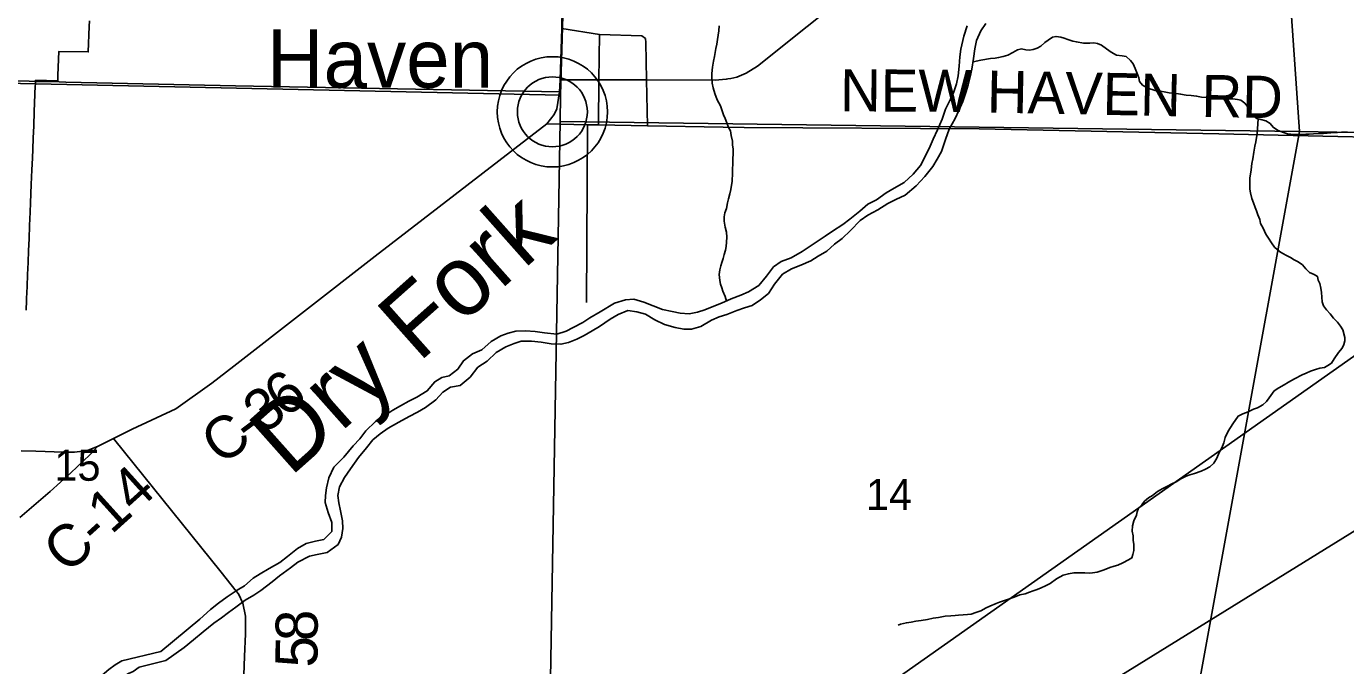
# Model space of a CAD drawing. Extents: x -7.5 to 26.5, y 3.5 to 25.5.
# Drawn here: x -1.65 to 0.131, y 22.311 to 23.173 of the extents above; entities that cross this region are included whole.
import ezdxf

# ---------------------------------------------------------------- set-up
doc = ezdxf.new("R2010")
doc.units = 0
for name, color, linetype in [('GM_X_Corporation', 7, 'Continuous'), ('GM_X_County_Road', 7, 'Continuous'), ('GM_X_County_Road_Text', 7, 'Continuous'), ('GM_X_Minor_River', 7, 'Continuous'), ('GM_X_Minor_River_Text', 7, 'Continuous'), ('GM_X_Section_Text', 7, 'Continuous'), ('GM_X_Township_Road', 7, 'Continuous'), ('GM_X_Unincorporated', 7, 'Continuous'), ('GM_X_Unincorporated_Location', 7, 'Continuous'), ('GM_X_Unincorporated_Text', 7, 'Continuous'), ('SH_Text', 7, 'Continuous')]:
    doc.layers.add(name, color=color, linetype=linetype)

msp = doc.modelspace()

# ---------------------------------------------------------------- linework, layer by layer
at = {"layer": 'GM_X_Corporation'}
for points in [[(-2.147, 24.1207), (-0.8988, 24.09), (-0.9286, 23.0807), (-2.1999, 23.1078)], [(-0.8988, 24.09), (-0.0024, 24.0614), (0.0689, 23.0315), (-0.9291, 23.0451), (-0.9286, 23.0807)], [(-0.0024, 24.0614), (1.0957, 24.0219), (1.0735, 23.0136), (0.0689, 23.0315)], [(-2.1999, 23.1078), (-0.9286, 23.0807), (-0.9291, 23.0451), (-0.9461, 22.0601), (-2.2479, 22.1217)], [(0.0689, 23.0315), (-0.1108, 22.0429), (-0.9461, 22.0601), (-0.9291, 23.0451)], [(1.0735, 23.0136), (1.0508, 22.0159), (-0.1108, 22.0429), (0.0689, 23.0315)]]:
    msp.add_lwpolyline(points, close=True, dxfattribs=at)
msp.add_lwpolyline([(-1.5642, 23.1808), (-1.5646, 23.1731), (-1.566, 23.1389), (-1.6056, 23.1397), (-1.6069, 23.1077), (-1.6073, 23.1001), (-1.6372, 23.1007), (-1.6374, 23.095), (-1.6375, 23.0932), (-1.6389, 23.0585), (-1.6397, 23.0394), (-1.6404, 23.0224), (-1.641, 23.0078), (-1.6415, 22.9955), (-1.6422, 22.9797), (-1.643, 22.9601), (-1.644, 22.9353), (-1.6445, 22.9228), (-1.6452, 22.9048), (-1.646, 22.8869), (-1.6466, 22.8709), (-1.6473, 22.8548), (-1.6479, 22.8387), (-1.6486, 22.8226), (-1.6493, 22.8065), (-1.6494, 22.8036), (-1.6499, 22.7904)], dxfattribs=at)
at = {"layer": 'GM_X_County_Road'}
for points in [[(-0.9268, 23.1706), (-0.9225, 23.418), (-0.9241, 23.4397), (-0.9294, 23.4683), (-0.9349, 23.4993), (-0.9361, 23.5122), (-0.9345, 23.5422), (-0.9252, 23.629), (-0.9207, 23.6517), (-0.9185, 23.6763), (-0.9147, 23.7286), (-0.9035, 24.1114), (-0.8973, 24.4)], [(-0.7027, 23.1025), (-0.6986, 23.1032), (-0.6906, 23.1047), (-0.6779, 23.1104), (-0.6624, 23.1199), (-0.5287, 23.2271), (-0.5239, 23.2334), (-0.5217, 23.2447), (-0.5167, 23.5532), (-0.5166, 23.5545), (-0.5162, 23.5554), (-0.5157, 23.556), (-0.5147, 23.5562), (-0.4415, 23.5545), (-0.4014, 23.5536)], [(-0.9469, 23.0417), (-0.937, 23.0547), (-0.9337, 23.0622), (-0.9298, 23.0853), (-0.9292, 23.1013), (-0.9268, 23.1706)], [(-1.9187, 23.1051), (-1.6459, 23.0994), (-1.6361, 23.0992)], [(-1.6361, 23.0992), (-1.6055, 23.0985), (-1.5964, 23.0983)], [(-1.5964, 23.0983), (-1.3671, 23.0933), (-0.9298, 23.0853)], [(-0.9292, 23.1013), (-0.8766, 23.1012), (-0.8125, 23.1011), (-0.7199, 23.101), (-0.7047, 23.1021), (-0.7027, 23.1025)], [(-1.6568, 22.6007), (-1.6367, 22.6004), (-1.5995, 22.5991), (-1.5848, 22.5989), (-1.5737, 22.6001), (-1.5662, 22.6016), (-1.5536, 22.6067), (-1.5321, 22.6175), (-1.5067, 22.63), (-1.4479, 22.6575), (-1.3991, 22.6922), (-1.3695, 22.7151), (-1.1787, 22.8635), (-0.9469, 23.0417)], [(-0.9469, 23.0417), (-0.8922, 23.0406), (-0.8774, 23.0404), (-0.8113, 23.0391), (-0.7088, 23.0372), (-0.6806, 23.037)], [(-0.6806, 23.037), (-0.3636, 23.035), (-0.0398, 23.0286), (0.3216, 23.0203), (0.4815, 23.0211), (0.5343, 23.0188), (0.5601, 23.0196)], [(-1.5321, 22.6175), (-1.3864, 22.4372), (-1.3664, 22.4116)], [(-1.6586, 22.5107), (-1.6175, 22.5459), (-1.5895, 22.5709), (-1.5639, 22.5954), (-1.5536, 22.6067)], [(-1.3664, 22.4116), (-1.3634, 22.4078), (-1.3573, 22.3951), (-1.3536, 22.3776), (-1.3537, 22.3538), (-1.3551, 22.3235), (-1.357, 22.2734), (-1.3582, 22.2401), (-1.3559, 22.2141), (-1.3534, 22.189), (-1.3562, 22.1733), (-1.3625, 22.1603), (-1.367, 22.149), (-1.3698, 22.1381), (-1.3703, 22.1249), (-1.37, 22.1014), (-1.3684, 22.0877), (-1.3657, 22.0829), (-1.3613, 22.0799), (-1.3528, 22.0783), (-1.255, 22.073), (-1.1558, 22.0672)]]:
    msp.add_lwpolyline(points, dxfattribs=at)
at = {"layer": 'GM_X_Minor_River'}
for points in [[(-0.3798, 23.174), (-0.3843, 23.1601), (-0.3881, 23.1426), (-0.3895, 23.1324), (-0.3902, 23.1195), (-0.3917, 23.1066), (-0.3942, 23.096), (-0.3976, 23.085), (-0.402, 23.0753), (-0.4088, 23.0617), (-0.4133, 23.0482), (-0.4197, 23.0339), (-0.4254, 23.0214), (-0.4294, 23.0117), (-0.4358, 22.9989), (-0.4426, 22.9857), (-0.4524, 22.9742), (-0.4645, 22.9627), (-0.478, 22.955), (-0.4888, 22.9488), (-0.5019, 22.9393), (-0.5138, 22.9335), (-0.5247, 22.9239), (-0.5379, 22.9135), (-0.5476, 22.9062), (-0.5615, 22.897), (-0.5715, 22.8904), (-0.582, 22.8831), (-0.5928, 22.8761), (-0.6025, 22.8695), (-0.6171, 22.8611), (-0.6305, 22.8561), (-0.641, 22.8492), (-0.6504, 22.8365), (-0.661, 22.8238), (-0.6749, 22.8154), (-0.6853, 22.8107), (-0.6983, 22.8057), (-0.7114, 22.7999), (-0.7214, 22.796), (-0.7336, 22.791), (-0.7436, 22.7878), (-0.7547, 22.7858), (-0.7672, 22.7865), (-0.7778, 22.7887), (-0.791, 22.7913), (-0.8034, 22.7966), (-0.8162, 22.8014), (-0.8294, 22.8052), (-0.8409, 22.8047), (-0.8558, 22.7998), (-0.8751, 22.7881), (-0.889, 22.7801), (-0.8986, 22.7738), (-0.9113, 22.7673), (-0.921, 22.7622), (-0.9336, 22.758), (-0.9503, 22.7599), (-0.9628, 22.7618), (-0.976, 22.7628), (-0.989, 22.7624), (-0.9993, 22.7596), (-1.0093, 22.7557), (-1.022, 22.7484), (-1.0348, 22.7369), (-1.0475, 22.7315), (-1.0595, 22.7223), (-1.067, 22.7111), (-1.079, 22.7019), (-1.0886, 22.6995), (-1.0982, 22.694), (-1.1084, 22.6817), (-1.1223, 22.6733), (-1.1331, 22.6679), (-1.1447, 22.6617), (-1.1547, 22.6558), (-1.1682, 22.6467)], [(-1.1109, 22.6593), (-1.097, 22.6696), (-1.0876, 22.6797), (-1.0771, 22.6866), (-1.0638, 22.689), (-1.0506, 22.7), (-1.04, 22.7135), (-1.0276, 22.7219), (-1.0152, 22.7334), (-1.0024, 22.7411), (-0.9913, 22.7457), (-0.9817, 22.7489), (-0.9677, 22.7489), (-0.9548, 22.7475), (-0.9411, 22.7452), (-0.9279, 22.7445), (-0.9179, 22.7469), (-0.9064, 22.7512), (-0.8964, 22.7563), (-0.8856, 22.7625), (-0.876, 22.7687), (-0.8613, 22.7782), (-0.8508, 22.7848), (-0.8378, 22.7902), (-0.8253, 22.7884), (-0.8136, 22.785), (-0.8013, 22.7775), (-0.7881, 22.7711), (-0.7738, 22.7673), (-0.762, 22.7651), (-0.7518, 22.7648), (-0.7391, 22.7687), (-0.7249, 22.7771), (-0.7145, 22.7814), (-0.7038, 22.7849), (-0.6904, 22.7899), (-0.68, 22.7935), (-0.67, 22.797), (-0.6584, 22.8047), (-0.6476, 22.8132), (-0.6397, 22.8255), (-0.6287, 22.839), (-0.6167, 22.8463), (-0.6041, 22.8513), (-0.5906, 22.857), (-0.5806, 22.8632), (-0.569, 22.8702), (-0.5589, 22.8794), (-0.5484, 22.8872), (-0.5372, 22.8979), (-0.5239, 22.9117), (-0.5138, 22.9186), (-0.5004, 22.9259), (-0.4868, 22.9343), (-0.4757, 22.9398), (-0.4634, 22.9459), (-0.4486, 22.9581), (-0.4369, 22.9707), (-0.4259, 22.9845), (-0.42, 22.9943), (-0.4144, 23.0048), (-0.4087, 23.021), (-0.4038, 23.0346), (-0.3958, 23.0492), (-0.391, 23.0598), (-0.3853, 23.0722), (-0.3816, 23.0843), (-0.3783, 23.0945), (-0.3754, 23.1054), (-0.3732, 23.1156), (-0.371, 23.13), (-0.3691, 23.1433), (-0.3669, 23.1543), (-0.3613, 23.1675), (-0.3542, 23.1772)], [(-0.7046, 22.8025), (-0.7064, 22.809), (-0.7093, 22.8162), (-0.7107, 22.8208), (-0.7125, 22.8254), (-0.7136, 22.8304), (-0.7142, 22.8388), (-0.7133, 22.8449), (-0.7121, 22.8502), (-0.7108, 22.8547), (-0.7088, 22.8604), (-0.7076, 22.8657), (-0.706, 22.8714), (-0.7051, 22.8764), (-0.7043, 22.8824), (-0.7038, 22.8889), (-0.7044, 22.8958), (-0.7062, 22.9023), (-0.7075, 22.9107), (-0.7074, 22.9164), (-0.7066, 22.9217), (-0.7046, 22.9278), (-0.7029, 22.9354), (-0.7017, 22.9407), (-0.7, 22.9475), (-0.6988, 22.9532), (-0.697, 22.9646), (-0.6965, 22.9753), (-0.6964, 22.9802), (-0.6958, 22.9886), (-0.6955, 23.0076), (-0.6962, 23.0134), (-0.6964, 23.0187), (-0.6982, 23.0263), (-0.6992, 23.0325), (-0.7018, 23.0371), (-0.704, 23.0432), (-0.7062, 23.0489), (-0.7084, 23.0539), (-0.7127, 23.0662), (-0.7171, 23.0743), (-0.72, 23.0827), (-0.7225, 23.0904), (-0.7239, 23.0969), (-0.7242, 23.1052), (-0.7241, 23.1098), (-0.7232, 23.1182), (-0.7219, 23.1265), (-0.7206, 23.1326), (-0.7189, 23.1436), (-0.7173, 23.1493), (-0.7164, 23.1558), (-0.715, 23.1676), (-0.7142, 23.174)], [(-0.3717, 23.1256), (-0.361, 23.1279), (-0.348, 23.13), (-0.3419, 23.1306), (-0.3373, 23.1313), (-0.3308, 23.1327), (-0.3247, 23.1346), (-0.3178, 23.1383), (-0.3116, 23.1416), (-0.3063, 23.143), (-0.3002, 23.1418), (-0.2956, 23.1413), (-0.2903, 23.142), (-0.2849, 23.1438), (-0.2803, 23.1468), (-0.2749, 23.1516), (-0.2703, 23.1546), (-0.2645, 23.1587), (-0.2595, 23.1598), (-0.2531, 23.1589), (-0.2485, 23.1577), (-0.2436, 23.1557), (-0.2368, 23.1533), (-0.2322, 23.1525), (-0.2224, 23.1508), (-0.214, 23.1507), (-0.2087, 23.1513), (-0.2037, 23.1505), (-0.1984, 23.1481), (-0.1917, 23.1431), (-0.1853, 23.1384), (-0.1781, 23.1345), (-0.1705, 23.1336), (-0.1648, 23.1327), (-0.1592, 23.1273), (-0.1555, 23.1227), (-0.1526, 23.1165), (-0.15, 23.11), (-0.1479, 23.1039), (-0.1468, 23.0989), (-0.1427, 23.0943), (-0.1355, 23.09), (-0.1257, 23.0871), (-0.1189, 23.0859), (-0.1136, 23.085), (-0.1067, 23.0838), (-0.1003, 23.0833), (-0.0915, 23.082), (-0.0839, 23.0807), (-0.0771, 23.0802), (-0.0699, 23.0794), (-0.0631, 23.0781), (-0.057, 23.0776), (-0.0524, 23.0772), (-0.0441, 23.0759), (-0.0342, 23.0757), (-0.0277, 23.0756), (-0.0208, 23.0755), (-0.0148, 23.0747), (-0.0102, 23.0738), (-0.005, 23.0696), (0.0002, 23.0634), (0.0017, 23.0588), (0.0046, 23.0542), (0.0114, 23.0491), (0.0167, 23.0479), (0.0235, 23.0459), (0.0292, 23.0423), (0.0333, 23.0373), (0.0393, 23.0334), (0.0461, 23.0306), (0.0529, 23.0286), (0.0624, 23.0277), (0.0674, 23.0276), (0.0776, 23.0278), (0.0822, 23.0281), (0.0879, 23.0284), (0.0952, 23.0287), (0.1013, 23.029), (0.1112, 23.03), (0.1203, 23.0302), (0.1257, 23.0309), (0.1333, 23.0311)], [(0.013, 23.0487), (0.0123, 23.035), (0.0118, 23.0289), (0.0101, 23.0175), (0.0088, 23.0118), (0.0075, 23.0038), (0.0062, 22.9947), (0.0046, 22.9886), (0.0037, 22.9799), (0.0019, 22.9685), (0.0018, 22.9609), (0.0021, 22.9536), (0.0027, 22.949), (0.0045, 22.9414), (0.0067, 22.9353), (0.0092, 22.9291), (0.011, 22.9245), (0.0128, 22.9192), (0.0154, 22.9127), (0.0164, 22.9073), (0.0198, 22.9012), (0.0234, 22.8931), (0.0271, 22.8877), (0.0312, 22.8812), (0.0353, 22.8754), (0.042, 22.8699), (0.0465, 22.8672), (0.0514, 22.8645), (0.0567, 22.8617), (0.062, 22.8586), (0.0673, 22.8558), (0.0729, 22.8519), (0.0774, 22.8461), (0.0826, 22.8415), (0.0887, 22.8387), (0.0932, 22.836), (0.0942, 22.831), (0.0964, 22.8264), (0.0978, 22.8203), (0.0985, 22.8145), (0.0994, 22.802), (0.1012, 22.7966), (0.1053, 22.7908), (0.1105, 22.7854), (0.115, 22.7796), (0.1202, 22.7742), (0.1243, 22.7688), (0.1273, 22.7638), (0.1301, 22.7538), (0.13, 22.7493), (0.1288, 22.7443), (0.1268, 22.7394), (0.1218, 22.7334), (0.1159, 22.7251), (0.1124, 22.7191), (0.1074, 22.7157), (0.1027, 22.7131), (0.0966, 22.7121), (0.0905, 22.7103), (0.084, 22.7081), (0.0782, 22.7055), (0.0725, 22.7034), (0.0621, 22.6978), (0.054, 22.6934), (0.0483, 22.69), (0.0413, 22.6856), (0.0348, 22.6815), (0.0281, 22.6721), (0.0246, 22.6672), (0.0196, 22.6627), (0.0123, 22.659), (0.0069, 22.6568), (-0.0004, 22.6535), (-0.0077, 22.6506), (-0.0138, 22.6476), (-0.0208, 22.6371), (-0.0271, 22.6273), (-0.0315, 22.6189), (-0.0331, 22.6114), (-0.0359, 22.6049), (-0.0394, 22.5985), (-0.0426, 22.5909), (-0.0466, 22.5841), (-0.052, 22.5793), (-0.0577, 22.5759), (-0.0639, 22.5734), (-0.0727, 22.5701), (-0.0792, 22.5683), (-0.0838, 22.5665), (-0.0911, 22.5632), (-0.0973, 22.5591), (-0.1034, 22.5561), (-0.1092, 22.5532), (-0.1153, 22.5498), (-0.1226, 22.5461), (-0.1296, 22.5405), (-0.135, 22.5372), (-0.14, 22.5327), (-0.1439, 22.5278), (-0.1485, 22.5233), (-0.1502, 22.5184)], [(-1.4611, 22.318), (-1.4367, 22.3353), (-1.4239, 22.3457), (-1.4107, 22.3567), (-1.3967, 22.3682), (-1.3863, 22.3755), (-1.3766, 22.3825), (-1.3669, 22.3899), (-1.3542, 22.3991), (-1.3426, 22.406), (-1.3329, 22.4122), (-1.3178, 22.424), (-1.3077, 22.4322), (-1.293, 22.4428), (-1.283, 22.4506), (-1.2672, 22.4585), (-1.2572, 22.4609), (-1.2435, 22.4636), (-1.2288, 22.4743), (-1.2243, 22.4841), (-1.2225, 22.4958), (-1.223, 22.5065), (-1.2254, 22.5199), (-1.2277, 22.5306), (-1.229, 22.5405), (-1.2268, 22.5523), (-1.22, 22.5647), (-1.2121, 22.5766), (-1.2011, 22.5916), (-1.1905, 22.605), (-1.1819, 22.6154), (-1.1718, 22.6239), (-1.161, 22.6313), (-1.1467, 22.6393), (-1.1329, 22.6469), (-1.1217, 22.6531), (-1.1109, 22.6593)], [(-1.1682, 22.6467), (-1.1783, 22.6405), (-1.1915, 22.6279), (-1.1994, 22.617), (-1.2083, 22.6074), (-1.2209, 22.5921), (-1.2345, 22.5787), (-1.2413, 22.5644), (-1.2443, 22.5508), (-1.2457, 22.5406), (-1.2464, 22.5311), (-1.2421, 22.5176), (-1.2371, 22.5042), (-1.2371, 22.492), (-1.248, 22.4813), (-1.2594, 22.4789), (-1.2717, 22.4758), (-1.2836, 22.4692), (-1.2972, 22.4581), (-1.3073, 22.45), (-1.3219, 22.442), (-1.3339, 22.4347), (-1.3435, 22.4289), (-1.3552, 22.4185), (-1.3648, 22.4127), (-1.3784, 22.4039), (-1.39, 22.3954), (-1.4012, 22.3869), (-1.4152, 22.3736), (-1.4682, 22.3301)], [(-0.1502, 22.5184), (-0.151, 22.5138), (-0.1546, 22.5063), (-0.1562, 22.4998), (-0.1567, 22.4922), (-0.1557, 22.4861), (-0.1554, 22.4804), (-0.1548, 22.4743), (-0.1545, 22.4663), (-0.1558, 22.461), (-0.1574, 22.4564), (-0.162, 22.4538), (-0.1693, 22.4498), (-0.1762, 22.4464), (-0.1812, 22.445), (-0.1869, 22.4432), (-0.1946, 22.4403), (-0.2042, 22.437), (-0.2103, 22.436), (-0.2149, 22.4356), (-0.2206, 22.4361), (-0.2282, 22.4362), (-0.2354, 22.436), (-0.243, 22.435), (-0.2499, 22.4332), (-0.2592, 22.428), (-0.2676, 22.4216), (-0.2738, 22.4187), (-0.2795, 22.4161), (-0.2849, 22.4135), (-0.2903, 22.4121), (-0.2956, 22.4103), (-0.3014, 22.4077), (-0.3083, 22.4063), (-0.3163, 22.4034), (-0.3236, 22.4008), (-0.3294, 22.3987), (-0.3359, 22.3965), (-0.3405, 22.395), (-0.3489, 22.391), (-0.3539, 22.3888), (-0.3612, 22.3851), (-0.3681, 22.3825), (-0.3742, 22.3803), (-0.3792, 22.38), (-0.3849, 22.3794), (-0.3914, 22.3791), (-0.396, 22.3784), (-0.4017, 22.3781), (-0.4093, 22.3775), (-0.4181, 22.3761), (-0.4253, 22.3751), (-0.433, 22.3733), (-0.4418, 22.3719), (-0.449, 22.3709), (-0.4551, 22.3698), (-0.4616, 22.3688), (-0.4696, 22.367), (-0.4729, 22.3656)], [(-1.4682, 22.3301), (-1.5209, 22.3176), (-1.5298, 22.3121), (-1.5384, 22.3057), (-1.5472, 22.2981), (-1.5538, 22.2839), (-1.5559, 22.2696), (-1.5557, 22.2604), (-1.5545, 22.2482), (-1.5544, 22.2416)], [(-1.5544, 22.242), (-1.5545, 22.2482), (-1.5557, 22.2604), (-1.5559, 22.2696), (-1.5538, 22.2839), (-1.5472, 22.2981), (-1.5384, 22.3057), (-1.5298, 22.3121), (-1.5209, 22.3176), (-1.4682, 22.3301)], [(-1.5349, 22.2425), (-1.535, 22.2494), (-1.5362, 22.2616), (-1.5364, 22.2684), (-1.5349, 22.2782), (-1.5313, 22.2861), (-1.5262, 22.2905), (-1.5188, 22.2959), (-1.5118, 22.3003), (-1.5053, 22.3031), (-1.4971, 22.3089), (-1.4611, 22.318)]]:
    msp.add_lwpolyline(points, dxfattribs=at)
at = {"layer": 'GM_X_Township_Road'}
msp.add_line((-0.8922, 23.0406), (-0.8933, 22.8007), dxfattribs=at)
for points in [[(-0.9268, 23.1706), (-0.8758, 23.1624), (-0.8189, 23.1608), (-0.814, 23.1572)], [(-0.8774, 23.0404), (-0.8766, 23.1012), (-0.8758, 23.1624)], [(-0.814, 23.1572), (-0.8134, 23.1515), (-0.8125, 23.1011), (-0.8113, 23.0391)]]:
    msp.add_lwpolyline(points, dxfattribs=at)
at = {"layer": 'GM_X_Unincorporated'}
for radius in [0.0744, 0.0472]:
    msp.add_circle((-0.9395, 23.0581), radius, dxfattribs=at)
at = {"layer": 'GM_X_Unincorporated_Location'}
msp.add_line((-0.9395, 23.0581), (-0.9395, 23.0581), dxfattribs=at)
at = {"layer": 'SH_Text'}
msp.add_lwpolyline([(2.4449, 24.351), (-2.5961, 20.7995), (2.4449, 23.9163)], close=True, dxfattribs=at)

# ---------------------------------------------------------------- texts
at = {"layer": 'GM_X_County_Road_Text'}
for s, height, rotation, p in [('NEW', 0.05682, 359.6986, (-0.5512, 23.0588)), ('HAVEN', 0.05682, 358.8617, (-0.3534, 23.0572)), ('RD', 0.05682, 359.0139, (-0.0637, 23.0513)), ('6', 0.0568, 37.7481, (-1.3004, 22.6437)), ('3', 0.0568, 37.3704, (-1.3286, 22.6222)), ('C', 0.0568, 35.4718, (-1.3869, 22.58)), ('-', 0.0568, 36.682, (-1.3479, 22.6078)), ('C-14', 0.05682, 42.089, (-1.5943, 22.4332)), ('8', 0.0568, 89.961, (-1.2563, 22.3442)), ('5', 0.0568, 89.0226, (-1.2569, 22.3082))]:
    msp.add_text(s, height=height, rotation=rotation, dxfattribs=at).set_placement(p)
at = {"layer": 'GM_X_Minor_River_Text'}
msp.add_text('Dry Fork', height=0.0947, rotation=41.6565, dxfattribs=at).set_placement((-1.2935, 22.5646))
at = {"layer": 'GM_X_Section_Text'}
for s, p in [('15', (-1.6117, 22.5604)), ('14', (-0.5163, 22.521))]:
    msp.add_text(s, height=0.04186, rotation=0, dxfattribs=at).set_placement(p)
at = {"layer": 'GM_X_Unincorporated_Text'}
msp.add_text('Haven', height=0.07898, rotation=0, dxfattribs=at).set_placement((-1.3247, 23.0906))

doc.saveas('drawing.dxf')
